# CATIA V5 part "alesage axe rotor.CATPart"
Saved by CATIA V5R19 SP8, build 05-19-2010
Part number: alesageaxerotor
Bounding box of the stored display mesh (mm): x -120 to 120, y -120 to 120, z -200 to 400
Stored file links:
  G:\EU_thinkMotion\CFAO_2010\St2M_groupe2\St2M_groupe2\npeyre\npeyre\alesage axe rotor.CATPart
  C:\Documents and Settings\Niels\Mes documents\IFMA\2A\Calculs et CFAO\Modélisation eolienne axe vertical\eolienne avec train reducteur\assemblage.CATProduct
  C:\Program Files\Dassault Systemes\B19\intel_a\startup\materials\French\Catalog.CATMaterial
  C:\Program Files\Dassault Systemes\B19\intel_a\startup\materials\blue_env_512x512.jpg
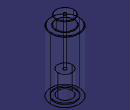
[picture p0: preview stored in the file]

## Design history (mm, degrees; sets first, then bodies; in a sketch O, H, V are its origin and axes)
Parameters
  `Diametre alesage rotor` = 30 mm
  `epaisseur alesage rotor` = 60 mm
  `Longueur alesage rotor` = 400 mm
  `Diametre primitif porte satellite` = 120 mm
  `Distance axe-contact sortie/carter` = 90 mm {= 0.5*`epaisseur alesage rotor` + `Diametre primitif porte satellite`/2}
Pad1: profile end face of Pad3, direction along axis of face of Pad2 from Sketch1.A2, length 300 {= `Longueur alesage rotor` *0.75}
Body1 (main body), material "Aucun"
  Sketch1 on xy-plane, origin (0, 0, 0), H (1, 0, 0), V (0, 1, 0)
    circle A1 centre (0, 0) radius 15
    circle A2 centre (0, 0) radius 75
    radius A1 = 15 {= `Diametre alesage rotor` /2}
    radius A2 = 75 {= `Diametre alesage rotor` /2 +`epaisseur alesage rotor`}
  Pad2: profile Sketch1, direction (0, 0, 1), length 400 {= `Longueur alesage rotor`}
  Sketch2 on xy-plane, origin (0, 0, 0), H (1, 0, 0), V (0, 1, 0)
    circle A1 centre (0, 0) radius 120
    circle A2 centre (0, 0) radius 60
    distance A2 A1 = 60 {= `epaisseur alesage rotor`}
    radius A2 = 60 {= `Diametre primitif porte satellite` /2}
  Sketch3 on xy-plane, origin (0, 0, 0), H (1, 0, 0), V (0, 1, 0)
    circle A1 centre (0, 0) radius 75
    circle A2 centre (0, 0) radius 120
    radius A1 = 75 {= `Diametre alesage rotor` /2 +`epaisseur alesage rotor`}
    radius A2 = 120 {= `epaisseur alesage rotor` +`Diametre primitif porte satellite` /2}
  Pad3: profile Sketch3, direction (0, 0, 1), length 20
  Pad4: profile Sketch2, direction (0, 0, -1), length 200
  Sketch4 on end face of Pad4, origin (-1.3216, -52.2899, -200), H (1, 0, 0), V (0, -1, 0)
    point P1 (1.3216, -52.2899)
    reference intersected line E1 through (0, -52.2899) direction (1, 0) from zx-plane
    reference intersected line E2 through (1.3216, 0) direction (0, 1) from yz-plane
    coincidence: P1 E1, P1 E2
  Hole1: placed by Sketch4, at (0, 0, -200) direction (0, 0, 1), diameter 180 {= `Diametre primitif porte satellite`+`epaisseur alesage rotor`}, depth 10
  Fillet1: radius 5, on edge [face of Pad2 from Sketch1.A2 | end face of Pad2]; edge [face of Pad1 | end face of Pad1]; edge [end face of Pad1 | face of Pad2 from Sketch1.A2]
